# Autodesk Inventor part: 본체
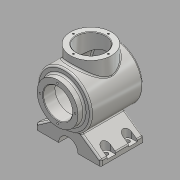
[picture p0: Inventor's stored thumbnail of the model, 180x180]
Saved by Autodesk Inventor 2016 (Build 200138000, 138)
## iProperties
Created: 2017-04
Part Number: 본체
Material: 알루미늄 6061
Document SubType Name: Modeling
Designer: CAMTIC
Density: 2.7 g/cm^3
Appearance: 알루미늄 - 평지
Mass: 1664.52 g
Surface Area: 1066.89 cm^2
Volume: 616.49 cm^3
Author: CAMTIC
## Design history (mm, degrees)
sketch "스케치1"
  geometry: L1 (-50, 50)-(46.336, 50); L2 (46.336, 50)-(46.336, 0); L3 (46.336, 0)-(-50, 0); L4 (-50, 0)-(-50, 50); L5 (-50, 0)-(-62, 0); L6 (-62, 0)-(-62, 38); L7 (-62, 38)-(-50, 38); L8 (-50, 38)-(-50, 0); L9 (46.336, 0)-(58, 0); A1 r 113 centre (-55, 0) between (58, 0) and (46.336, 50); 1 further point
  constraints: 18 end point, 4 parallel, 3 horizontal, 3 point on line, 2 perpendicular, 2 point on circle, 1 centre point
  dimensions: "d1" = 113 radius of A1; "d3" = 12 distance of L6.end L7.end; "d4" = 100 diameter of L1 L3; "d5" = 76 diameter of L7 L3; "d6" = 108 horizontal distance of L1.start L9.end; "d7" = 62 distance of point (0, 0) L5.end
revolve "회전1" sketch "스케치1" stored, may be unused: angle "d8" = 90 deg
sketch "스케치2"
  geometry: C1 r 38 at (0, 0); 1 further point
  constraints: 1 centre point, 1 coincident
  dimensions: "d9" = 76 diameter of C1
extrude "돌출1" join sketch "스케치2" distance "d10" = 65; taper "d11" = 0 deg
sketch "스케치3"
  geometry: 1 further point
node "작업 평면4"
sketch "스케치14"
  geometry: L1 (0, -29.988)-(-60, -72); L2 (-60, -72)-(-60, -82); L3 (-60, -82)-(60, -82); L4 (60, -82)-(60, -72); L5 (60, -72)-(0, -29.988); 2 further points
  constraints: 10 end point, 2 perpendicular, 2 vertical alignment, 1 equal length, 1 vertical
  dimensions: "d109" = 10 distance of L3.end L4.end; "d110" = 120 distance of L2.end L3.end; "d111" = 10 distance of L1.end L2.end; "d112" = 55 deg angle of L5 L4; "d113" = 82 distance from line of point (0, 0) L3
extrude "돌출5" join sketch "스케치14" distance "d114" = 80; taper "d115" = 0 deg
sketch "스케치5"
  geometry: L1 (-50, 50)-(46.336, 50) reference; L2 (-50, -50)-(-50, 50) reference; L3 (-40, 0)-(-40, 40); L4 (-40, 40)-(39.916, 40); L5 (-40, 0)-(48, 0); A1 r 113 centre (-55, 0) between (46.336, -50) and (46.336, 50) reference; A2 r 103 centre (-55, 0) between (48, 0) and (39.916, 40); 1 further point
  constraints: 6 end point, 2 horizontal alignment, 2 point on circle, 1 centre point, 1 horizontal, 1 other
  dimensions: "d19" = 10 radial gap between concentric circles of A1 A2; "d21" = 10 distance between parallel lines of L1 L4
revolve "회전2" sketch "스케치5" stored, may be unused: angle "d22" = 90 deg
hole "구멍1" diameter "d25" = 54; stored, may be unused: countersink angle "d29" = 90 deg, drill point angle "d31" = 118 deg; dims "d26" = 6, "d27" = 4, "d28" = 2, "d30" = 8, "d98" = 10, "d99" = 10
hole "구멍2" diameter "d34" = 54; stored, may be unused: countersink angle "d38" = 90 deg, drill point angle "d40" = 118 deg; dims "d32" = 10, "d33" = 10, "d35" = 6, "d36" = 4, "d37" = 2, "d39" = 8
sketch "스케치8"
  geometry: L1 (0, 0)-(0, 32.5)
  constraints: 2 end point, 1 vertical
  dimensions: "d69" = 32.5 distance of L1.start L1.end
hole "구멍5" sketch "스케치8" at (0, 32.5) diameter "d70" = 3.242; stored, may be unused: countersink angle "d74" = 90 deg, drill point angle "d76" = 118 deg; dims "d71" = 8, "d72" = 4, "d73" = 2, "d75" = 10
sketch "스케치9"
  geometry: L1 (0, 0)-(0, -32.5)
  constraints: 2 end point, 1 vertical
  dimensions: "d80" = 32.5 distance of L1.start L1.end
hole "구멍6" sketch "스케치9" at (0, -32.5) diameter "d81" = 3.242; stored, may be unused: countersink angle "d85" = 90 deg, drill point angle "d87" = 118 deg; dims "d82" = 8, "d83" = 4, "d84" = 2, "d86" = 10
chamfer "모따기1" distance "d94" = 1; stored, may be unused: second distance "d95" = 2, angle "d96" = 45 deg
fillet "모깎기1" dims "d97" = 3
fillet "모깎기2" dims "d100" = 3
node "작업 평면2"
node "작업 평면5"
sketch "스케치15"
  geometry: L1 (120, 0)-(120, 80) reference; L2 (110, 20)-(120, 20); L3 (110, 12)-(120, 12); L4 (120, 28)-(110, 28); L5 (120, 0)-(0, 0) reference; L6 (0, 80)-(120, 80) reference; A1 r 8 centre (110, 20) between (110, 28) and (110, 12); A2 r 8 centre (120, 20) between (120, 12) and (120, 28); 2 further points
  constraints: 8 end point, 4 point on circle, 4 tangent, 2 centre point, 1 horizontal, 1 midpoint, 1 parallel, 1 point on line
  dimensions: "d117" = 8 radius of A1; "d118" = 20 distance from line of L2.start L5; "d119" = 10 distance from line of L1 L2.start
extrude "돌출6" cut sketch "스케치15" distance "d120" = 31.75; taper "d121" = 0 deg
hole "구멍7" diameter "d124" = 8; stored, may be unused: countersink angle "d128" = 90 deg, drill point angle "d130" = 118 deg; dims "d122" = 10, "d123" = 10, "d125" = 6, "d126" = 4, "d127" = 2, "d129" = 8
sketch "스케치16"
  geometry: L1 (-60, -82)-(60, -82) reference; C1 r 18 at (0, -82); 1 further point
  constraints: 1 centre point, 1 midpoint
  dimensions: "d137" = 36 diameter of C1
extrude "돌출7" cut sketch "스케치16" stored distance "d138" = 31.75; taper "d139" = 0 deg
fillet "모깎기6" dims "d143" = 3
fillet "모깎기7" dims "d144" = 3
fillet "모깎기8" dims "d145" = 3
node "작업 평면6"
sketch "스케치17"
  geometry: 2 further points
  constraints: 1 coincident, 1 other
feature "엠보싱2" sketch "스케치17" dims "d1" = 113, "d3" = 12, "d4" = 100, "d5" = 76, "d6" = 108, "d7" = 62, "d146" = 0.5, "d147" = 0
node "솔리드1"
pattern_circular "원형 패턴1" dims angle "d78" = 360 deg
pattern_circular "원형 패턴2" dims angle "d89" = 360 deg
pattern_linear "직사각형 패턴2"
mirror "대칭2"
other parameters: "d108" = -8, "d116" = -6
